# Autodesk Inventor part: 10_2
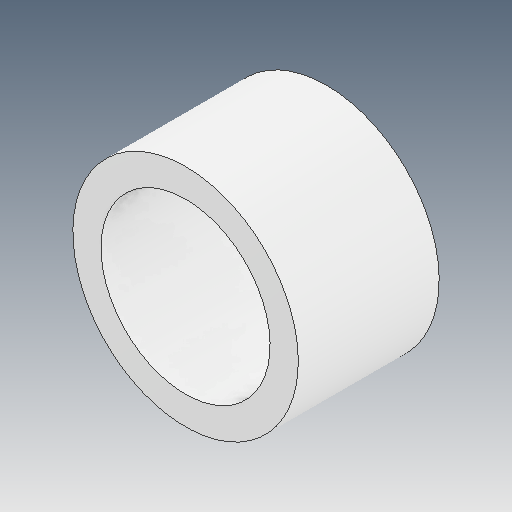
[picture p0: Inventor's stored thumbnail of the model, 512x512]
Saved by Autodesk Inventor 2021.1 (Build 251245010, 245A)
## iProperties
Created: 2021-06
Part Number: 10_2
Material: Ogólny
Document SubType Name: Modeling
Designer: user
Density: 1 g/cm^3
Appearance: Domyślna
Author: user
Revision Number: ÈÎºÎ
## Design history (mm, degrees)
feature "ÊäÈë1"
node "Bryła1"
